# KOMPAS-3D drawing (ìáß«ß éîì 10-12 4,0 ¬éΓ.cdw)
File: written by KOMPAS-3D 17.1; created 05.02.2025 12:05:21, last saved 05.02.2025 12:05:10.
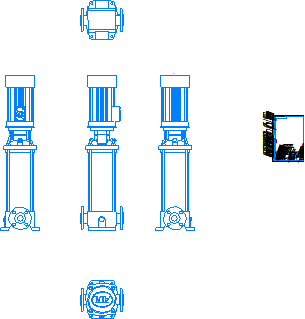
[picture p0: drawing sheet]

Sheet 1: A4, portrait

Title block, sheet 1: name: Насос ВМН 10-12 / 4,0 кВт; designation: Насос ВМН 10-12 4,0 кВт; material: Сталь 10  ГОСТ 1050-2013; mass: 186,96; sheets: 1; sheet format: A4; stored path: \\adlc.lan\data\АДЛ_ПКД\3D-модели\ADL production\Насосы ГРАНПАМП\Насосы ВМН\ВМН10\KOMPAS 3D\Насос ВМН 10-12 4,0 кВт.cdw

Views: Вид 1, Спереди, Проекционный вид 2, Проекционный вид 3, Проекционный вид 4, Проекционный вид 5
Referenced files in \\adlc.lan\data\АДЛ_ПКД\3D-модели\ADL production\Насосы ГРАНПАМП\Насосы ВМН\ВМН10\KOMPAS 3D\: Насос ВМН 10-12 4,0 кВт.m3d
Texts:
  Andrey
  АДЛ
Dimensions and other numbers on the sheet: 1:1; 1; 4,0 кВт; 186,96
